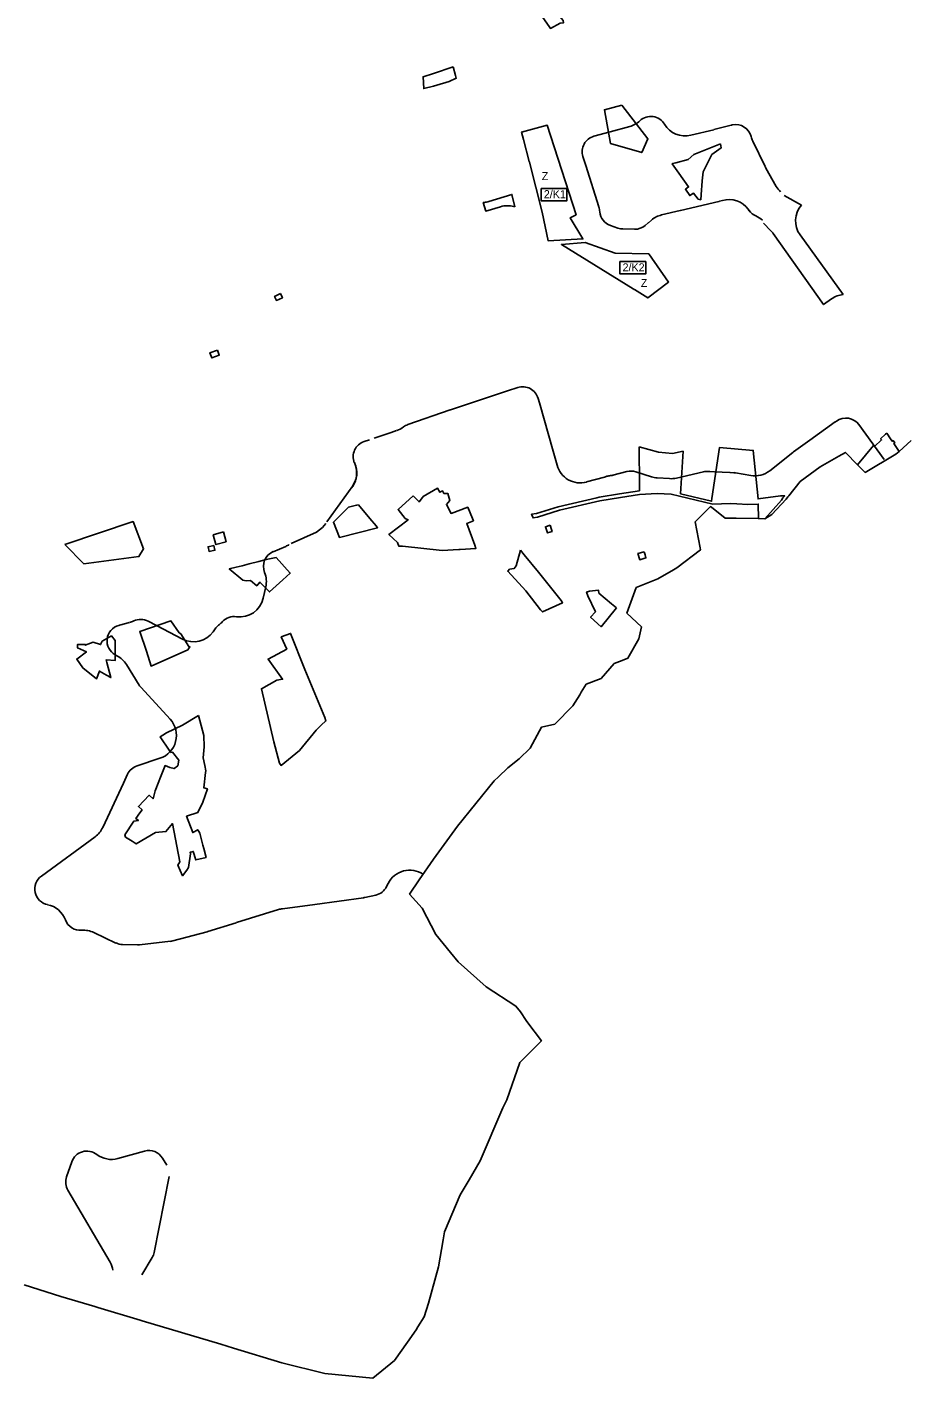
# Model space of a CAD drawing. Extents: x -445049 to -440454, y -1148980 to -1129741.
# Drawn here: x -444109 to -443013, y -1134562 to -1132874 of the extents above; entities that cross this region are included whole.
import ezdxf

# ---------------------------------------------------------------- set-up
doc = ezdxf.new("R2010")
doc.units = 0
for name, color, linetype in [('Vrstva 10', 7, 'Continuous'), ('Vrstva 23', 7, 'Continuous'), ('Vrstva 3', 7, 'Continuous'), ('Vrstva 4', 7, 'Continuous'), ('Vrstva 5', 7, 'Continuous'), ('Vrstva 7', 7, 'Continuous')]:
    doc.layers.add(name, color=color, linetype=linetype)

msp = doc.modelspace()

# ---------------------------------------------------------------- linework, layer by layer
at = {"layer": 'Vrstva 10'}
msp.add_lwpolyline([(-443488.7, -1133014.5), (-443481.6, -1133042.2), (-443481.3, -1133043.2), (-443465.2, -1133105.3), (-443458.1, -1133141.1), (-443414.4, -1133138.9), (-443430.2, -1133112.5), (-443423.1, -1133108.7), (-443459, -1132996.9), (-443491.2, -1133005.4)], close=True, dxfattribs=at)
for points in [[(-443350.1, -1133202.2), (-443333.3, -1133212.6), (-443307.4, -1133192.8), (-443332.2, -1133157.5), (-443374, -1133156.8), (-443411.5, -1133143.2), (-443441.4, -1133145.7), (-443351.7, -1133201.2)], [(-443351.7, -1133201.2), (-443350.4, -1133202)], [(-443350.4, -1133202), (-443350.1, -1133202.2)]]:
    msp.add_lwpolyline(points, dxfattribs=at)
at = {"layer": 'Vrstva 23'}
for p, q in [((-443380.3, -1133005), (-443356, -1132998.4)), ((-443279.4, -1133009.4), (-443251, -1133002.4)), ((-443250.6, -1133002.3), (-443229.1, -1132996.8)), ((-443228.1, -1132996.5), (-443227.4, -1132996.4)), ((-443400.7, -1133010.6), (-443380.4, -1133005)), ((-443202, -1133016.6), (-443186.8, -1133048.4)), ((-443411, -1133047), (-443414.4, -1133035.9)), ((-443394.7, -1133099), (-443410.9, -1133047)), ((-443185.8, -1133050.4), (-443172.7, -1133073.2)), ((-443162.9, -1133084.6), (-443141.3, -1133096.6)), ((-443499.6, -1133098.8), (-443500.8, -1133098.5)), ((-443292.7, -1133103.5), (-443316.1, -1133109)), ((-443244.5, -1133092.1), (-443292.6, -1133103.5)), ((-443240, -1133090.8), (-443243.7, -1133091.9)), ((-443206.6, -1133103.6), (-443207.8, -1133101.9)), ((-443332.7, -1133118.7), (-443336.6, -1133122)), ((-443328.7, -1133115.3), (-443332.6, -1133118.6)), ((-443179.4, -1133128.9), (-443188.7, -1133119.2)), ((-443370.7, -1133125.4), (-443380.1, -1133122.1)), ((-443350, -1133126.8), (-443364.5, -1133126.5)), ((-443143, -1133133.8), (-443089, -1133208.5)), ((-443580.1, -1133352.5), (-443508.6, -1133328.8)), ((-443508.6, -1133328.8), (-443496, -1133324.6)), ((-443470.4, -1133338.2), (-443468.9, -1133343.7)), ((-443633.3, -1133370.9), (-443580.4, -1133352.6)), ((-443468.9, -1133343.8), (-443451.7, -1133404)), ((-443098.9, -1133367.5), (-443097.4, -1133366.4)), ((-443069.5, -1133370.9), (-443037.8, -1133414.4)), ((-443688.1, -1133392.1), (-443681.1, -1133389.8)), ((-443688.1, -1133392.1), (-443682.5, -1133390.2)), ((-443675.3, -1133387.8), (-443654.3, -1133380.7)), ((-443654.3, -1133380.7), (-443647.3, -1133378.3)), ((-443451.6, -1133404.2), (-443446.8, -1133421.6)), ((-443180.9, -1133428.5), (-443152.1, -1133405.6)), ((-443409.9, -1133442.6), (-443387.3, -1133436.4)), ((-443376.9, -1133434.1), (-443359.4, -1133429.6)), ((-443348.4, -1133429.9), (-443328.7, -1133436.1)), ((-443321.6, -1133437.4), (-443306.4, -1133438.4)), ((-443297.6, -1133437.7), (-443263.9, -1133429.8)), ((-443258.4, -1133429.3), (-443255.8, -1133429.4)), ((-443255.7, -1133429.4), (-443250, -1133429.7)), ((-443250, -1133429.7), (-443230.8, -1133430.7)), ((-443230.6, -1133430.7), (-443225.9, -1133431)), ((-443223.8, -1133431.2), (-443204.7, -1133434.5)), ((-443734.6, -1133492.2), (-443702, -1133447.6)), ((-443779.1, -1133519.4), (-443747.5, -1133505.4)), ((-443801.7, -1133529.7), (-443786, -1133523.1)), ((-443814.1, -1133587.8), (-443810.9, -1133573.7)), ((-443994.5, -1133621.8), (-443993.7, -1133621.6)), ((-443993.7, -1133621.6), (-443986, -1133619.5)), ((-443986, -1133619.5), (-443981.5, -1133618.3)), ((-443876.7, -1133629.8), (-443873.2, -1133624.9)), ((-443996.3, -1133660.1), (-443999, -1133658.6)), ((-443969.1, -1133696.5), (-443985.2, -1133670.6)), ((-443930.5, -1133739.1), (-443966.9, -1133699.4)), ((-443971.9, -1133797.3), (-443943.2, -1133787.8)), ((-444091.4, -1133935), (-444024.2, -1133885.8)), ((-443658, -1133944.3), (-443659.9, -1133948.1)), ((-443688.7, -1133962), (-443749.6, -1133970.4)), ((-443673.5, -1133958.7), (-443687, -1133961.7)), ((-443795.1, -1133976.9), (-443847.7, -1133993.1)), ((-443749.7, -1133970.4), (-443790.2, -1133975.8)), ((-443847.9, -1133993.2), (-443883.4, -1134004.4)), ((-443998.2, -1134018.6), (-444025.9, -1134005.5)), ((-443884.3, -1134004.6), (-443927.2, -1134016)), ((-443971.2, -1134020.9), (-443990.1, -1134020.5)), ((-443930.1, -1134016.5), (-443968.6, -1134020.8)), ((-443995.8, -1134287.9), (-443962.5, -1134278.5)), ((-444059.9, -1134310.8), (-444053.4, -1134292)), ((-443939.9, -1134287.4), (-443934.6, -1134296.2)), ((-443931.7, -1134310.2), (-443950.4, -1134405.2)), ((-444005.6, -1134417.5), (-444058.3, -1134327.5)), ((-443952.8, -1134411.5), (-443965.8, -1134433.4))]:
    msp.add_line(p, q, dxfattribs=at)
for points in [[(-443532.2, -1133092.2), (-443503.2, -1133083.2), (-443499.6, -1133098.8)], [(-443517.4, -1133098.7), (-443536, -1133104.2), (-443539, -1133093.5), (-443537.4, -1133093.3)], [(-443103.8, -1133213.9), (-443113.6, -1133220.9), (-443176.6, -1133132.3)], [(-443151.3, -1133405), (-443130.7, -1133390.3), (-443099, -1133367.6)], [(-443703.3, -1133449.6), (-443699.8, -1133443.4), (-443698.1, -1133438.3), (-443697.5, -1133434.5), (-443697.5, -1133428.8), (-443698, -1133425), (-443698.8, -1133422.2), (-443700.2, -1133418.4)], [(-443747.5, -1133505.4), (-443740.1, -1133499.4), (-443735.8, -1133494.3)], [(-443958, -1133616.5), (-443947.5, -1133621.9), (-443915, -1133638.9)], [(-444014.8, -1133874.3), (-443988.8, -1133818.7), (-443983.7, -1133807.8)]]:
    msp.add_lwpolyline(points, dxfattribs=at)
msp.add_lwpolyline([(-444062.3, -1133520.6), (-444038.2, -1133545), (-443969.5, -1133535.7), (-443963.6, -1133526.2), (-443976.9, -1133492)], close=True, dxfattribs=at)
for centre, radius, start, end in [((-443329.5, -1133005.9), 20, 30.8136, 133.2656), ((-443363.8, -1132969.5), 30, 285.0708, 313.2656), ((-443286.6, -1132980.3), 30, 210.8136, 283.8005), ((-443258.1, -1132973.3), 30, 283.8005, 284.5276), ((-443224.1, -1133016.1), 20, 101.4436, 104.5276), ((-443223.4, -1133016), 20, 14.2371, 101.4436), ((-443395.4, -1133029.9), 20, 105.477, 197.5121), ((-443375.1, -1133024.3), 20, 105.0708, 105.477), ((-443175, -1133003.7), 30, 194.2371, 205.5455), ((-443439.6, -1133056), 30, 17.38, 17.5121), ((-443159.8, -1133035.5), 30, 205.5455, 209.8821), ((-443146.7, -1133058.3), 30, 209.8821, 226.7245), ((-443541.1, -1133063.6), 30, 277.0607, 287.2397), ((-443508.8, -1133127.4), 30, 74.5325, 106.7342), ((-443423.3, -1133108), 30, 5.5239, 17.38), ((-443297.2, -1133084), 20, 283.086, 283.374), ((-443249.1, -1133072.6), 20, 283.374, 285.539), ((-443231.9, -1133119.7), 30, 36.3383, 105.539), ((-443190.5, -1133091.7), 20, 216.3383, 246.7557), ((-443118.7, -1133116.3), 30, 138.9795, 215.8663), ((-443373.5, -1133103.2), 20, 185.5239, 250.7766), ((-443313.3, -1133141.5), 30, 130.1903, 130.4326), ((-443309.3, -1133138.2), 30, 103.086, 130.1903), ((-443210.2, -1133137.7), 30, 48.0185, 66.7557), ((-443364.1, -1133106.5), 20, 250.7766, 268.784), ((-443349.6, -1133106.8), 20, 268.784, 310.4326), ((-443201, -1133149.7), 30, 35.4139, 43.9419), ((-443086.4, -1133238.3), 30, 95.036, 125.4139), ((-443489.7, -1133343.6), 20, 15.6761, 108.4331), ((-443518.1, -1133300.3), 30, 288.3161, 288.4331), ((-443573.8, -1133371.5), 20, 108.3161, 109.0994), ((-443440, -1133335.6), 30, 195.6761, 195.9557), ((-443656.9, -1133349.9), 30, 288.7113, 307.1241), ((-443626.7, -1133389.8), 20, 109.0994, 127.1241), ((-443116.4, -1133343.2), 30, 305.6204, 305.8262), ((-443085.7, -1133382.7), 20, 36.0604, 125.8262), ((-443663.9, -1133352.3), 30, 288.6899, 288.7113), ((-443681.7, -1133411.1), 20, 108.6689, 201.6607), ((-443470.9, -1133409.5), 20, 15.2701, 15.9557), ((-443139.6, -1133421.3), 20, 125.615, 128.3723), ((-443726.3, -1133431.5), 29.2, 325.3968, 24.5589), ((-443417.9, -1133413.7), 30, 195.2701, 285.3949), ((-443395.3, -1133407.5), 30, 285.3949, 289.0956), ((-443378.9, -1133454.7), 20, 96.1778, 109.0956), ((-443384.3, -1133405), 30, 276.1778, 284.3857), ((-443354.4, -1133449), 20, 72.539, 104.3857), ((-443319.7, -1133407.5), 30, 252.539, 266.3185), ((-443304.4, -1133408.5), 30, 266.3185, 283.2162), ((-443259.4, -1133449.3), 20, 87.2484, 103.2162), ((-443256.8, -1133449.4), 20, 87.0859, 87.2484), ((-443248.5, -1133399.7), 30, 267.0859, 267.1026), ((-443231.8, -1133450.6), 20, 86.42, 87.1026), ((-443227.2, -1133450.9), 20, 80.1563, 86.42), ((-443199.6, -1133405), 30, 260.1563, 308.3723), ((-443797.6, -1133495.4), 30, 292.7175, 302.2779), ((-443793.9, -1133548.1), 20, 112.7175, 202.2863), ((-443840.2, -1133567.1), 30, 347.314, 22.2863), ((-443843.4, -1133581.2), 30, 261.899, 347.314), ((-443850.4, -1133630.7), 20, 81.899, 136.8487), ((-443989.4, -1133641.1), 20, 104.9329, 241.2863), ((-443988.6, -1133640.9), 20, 104.9278, 104.9329), ((-443980.8, -1133638.8), 20, 104.9064, 104.9278), ((-443989.2, -1133589.3), 30, 284.9064, 296.1072), ((-443967.2, -1133634.2), 20, 62.4796, 116.1072), ((-443857, -1133636.6), 20, 126.7808, 144.2729), ((-443886.9, -1133596.5), 30, 306.7808, 316.8487), ((-443901.1, -1133612.3), 30, 242.4843, 324.2729), ((-444010.7, -1133686.4), 30, 31.8759, 61.2863), ((-443952.1, -1133685.9), 20, 211.8759, 222.5089), ((-443952.6, -1133759.3), 30, 288.2831, 42.5089), ((-443965.6, -1133816.3), 20, 108.2831, 154.9668), ((-444042, -1133861.6), 30, 306.1984, 334.9589), ((-443631.1, -1133957.6), 30, 55.8038, 153.678), ((-444079.6, -1133951.1), 20, 126.1984, 258.4959), ((-443677.8, -1133939.2), 20, 282.5288, 333.678), ((-443691.4, -1133942.2), 20, 277.8092, 282.5288), ((-444089.6, -1134000.1), 30, 20.3417, 78.4959), ((-443786.2, -1134005.5), 30, 97.595, 107.1299), ((-443752.4, -1133950.6), 20, 277.595, 277.8092), ((-444042.7, -1133982.8), 20, 200.3417, 274.5583), ((-443838.9, -1134021.8), 30, 107.1299, 107.4963), ((-444038.7, -1134032.6), 30, 64.6655, 94.5583), ((-443889.4, -1133985.3), 20, 284.8518, 287.4963), ((-443989.6, -1134000.5), 20, 244.6655, 268.7454), ((-443970.8, -1134000.9), 20, 268.7454, 276.3369), ((-443932.3, -1133996.7), 20, 276.3369, 284.8518), ((-444034.5, -1134298.6), 20, 52.3247, 160.864), ((-444003.9, -1134259), 30, 232.3247, 285.7015), ((-443957.1, -1134297.8), 20, 31.1463, 105.7015), ((-444041, -1134317.4), 20, 160.864, 210.3258), ((-444031.5, -1134432.6), 30, 10.3353, 30.3258), ((-443970, -1134401.3), 20, 329.2942, 348.8542)]:
    msp.add_arc(centre, radius, start, end, dxfattribs=at)
at = {"layer": 'Vrstva 3'}
for points in [[(-443466.5, -1133075.8), (-443434.4, -1133075.8), (-443434.4, -1133091.2), (-443466.5, -1133091.2)], [(-443368.1, -1133167.2), (-443335.9, -1133167.2), (-443335.9, -1133182.6), (-443368.1, -1133182.6)]]:
    msp.add_lwpolyline(points, close=True, dxfattribs=at)
at = {"layer": 'Vrstva 5'}
msp.add_lwpolyline([(-444112.9, -1134445.6), (-444067.3, -1134460.2), (-444024.8, -1134472.9), (-444020.9, -1134474), (-443968, -1134489.8), (-443965.3, -1134490.6), (-443866.9, -1134520), (-443851.3, -1134524.7), (-443791, -1134543.3), (-443737, -1134556.5), (-443676.9, -1134562.1), (-443649.8, -1134540.2), (-443633.9, -1134517.4), (-443623.1, -1134502.1), (-443620.7, -1134498.1), (-443613, -1134485.6), (-443607.6, -1134468.5), (-443594.8, -1134423.4), (-443589.3, -1134389.5), (-443587.7, -1134379.4), (-443567.8, -1134333.2), (-443556.7, -1134314.5), (-443542.7, -1134290.9), (-443514.7, -1134224.7), (-443509.6, -1134214.4), (-443493.3, -1134168), (-443466.4, -1134140.8), (-443483.2, -1134118.2), (-443485.3, -1134115.3), (-443492.5, -1134104.8), (-443498.3, -1134097.4), (-443535.5, -1134073.4), (-443570.5, -1134042.3), (-443579.9, -1134030.6), (-443598.2, -1134007.9), (-443615.3, -1133975.2), (-443631.1, -1133957.6), (-443619, -1133939.8), (-443601.3, -1133913.7), (-443571.4, -1133872.6), (-443525.4, -1133816.1), (-443519.9, -1133810.9), (-443508.5, -1133799.8), (-443494.1, -1133788.5), (-443480.2, -1133775), (-443468.6, -1133753.3), (-443466.2, -1133748.9), (-443449.4, -1133745.1), (-443427.1, -1133722.1), (-443418.4, -1133708.5), (-443416.5, -1133705.4), (-443410.3, -1133695.4), (-443391.7, -1133688.2), (-443375.3, -1133669.3), (-443365.3, -1133665.5), (-443358.3, -1133662.8), (-443344.7, -1133638.5), (-443341.3, -1133623.4), (-443359.4, -1133606.5), (-443347.8, -1133574.5), (-443320.6, -1133563.8), (-443301.3, -1133552.4), (-443297.2, -1133549.9), (-443267.5, -1133527.5), (-443268, -1133524.7), (-443274.1, -1133492.3), (-443262.4, -1133480.8), (-443254.8, -1133473.4), (-443251.5, -1133475.9), (-443236.6, -1133487.6), (-443223, -1133487.8), (-443195.1, -1133488.4), (-443187.2, -1133488.5), (-443178.2, -1133483.2), (-443160.5, -1133463.9), (-443158.2, -1133461.2), (-443157.2, -1133459.9), (-443143, -1133442.1), (-443118, -1133423.7), (-443094.7, -1133410.5), (-443086.4, -1133405.7), (-443071.4, -1133421), (-443061.5, -1133430.7), (-443023.3, -1133407.9), (-443019.2, -1133404.3), (-443014, -1133399.8), (-443004.2, -1133390.8)], dxfattribs=at)
at = {"layer": 'Vrstva 7'}
for points in [[(-443451.5, -1132851.1), (-443464.6, -1132862.4), (-443456.8, -1132873.4), (-443455.1, -1132875.9), (-443443.1, -1132869.2), (-443438.8, -1132869), (-443439, -1132866.2)], [(-443576.6, -1132924), (-443601.3, -1132932.4), (-443614.2, -1132936.3), (-443613.5, -1132951), (-443601.2, -1132948), (-443596.9, -1132946.9), (-443581.6, -1132942.4), (-443572.9, -1132938.2), (-443573.8, -1132934.8)], [(-443365.7, -1132971.7), (-443387.5, -1132977.5), (-443379.8, -1133019.8), (-443341, -1133031), (-443333.3, -1133014)], [(-443242.5, -1133019.9), (-443275.6, -1133033.4), (-443282.8, -1133039.8), (-443298.4, -1133043.8), (-443302.3, -1133044.8), (-443303, -1133045.1), (-443294.6, -1133056.9), (-443282.3, -1133074), (-443286.4, -1133076.9), (-443280.8, -1133084.8), (-443276.3, -1133081.6), (-443270.5, -1133089.1), (-443267.2, -1133089.9), (-443266.2, -1133077.4), (-443265.7, -1133072.4), (-443265.2, -1133066.4), (-443264.3, -1133055.1), (-443263, -1133052.5), (-443253.5, -1133033.6), (-443241.8, -1133025.3)], [(-443792.4, -1133207.3), (-443799.9, -1133210.8), (-443797.7, -1133215.8), (-443790.1, -1133212.3)], [(-443871.2, -1133277.7), (-443880.8, -1133281.2), (-443878.5, -1133287.5), (-443869, -1133284)], [(-443034.7, -1133381.4), (-443036.3, -1133383), (-443042.4, -1133388.6), (-443041, -1133390), (-443049.8, -1133398.3), (-443051.1, -1133396.8), (-443071.4, -1133421), (-443061.5, -1133430.7), (-443023.3, -1133407.9), (-443019.2, -1133404.3), (-443025.8, -1133394.6), (-443024.7, -1133393.8), (-443026.7, -1133390.9), (-443027.8, -1133391.7), (-443029.8, -1133388.6)], [(-443344.3, -1133398.7), (-443343.9, -1133447.1), (-443343.9, -1133450.5), (-443343.9, -1133453.6), (-443368.6, -1133457.3), (-443394, -1133461.6), (-443397, -1133462.3), (-443445.4, -1133473.6), (-443472.6, -1133481.9), (-443478.7, -1133482.9), (-443476.7, -1133487.4), (-443471.1, -1133486.5), (-443443.7, -1133477.9), (-443393.4, -1133466.2), (-443367.4, -1133461.9), (-443343.8, -1133458.4), (-443321.8, -1133457.1), (-443304.3, -1133457.9), (-443252.2, -1133470.2), (-443230.3, -1133469.6), (-443222, -1133470), (-443208.1, -1133470.6), (-443195.3, -1133470.3), (-443195.1, -1133488.4), (-443187.2, -1133488.5), (-443166.1, -1133465.1), (-443164.5, -1133462.4), (-443162.2, -1133459.9), (-443167.4, -1133459.9), (-443195.5, -1133463.8), (-443201.6, -1133403.1), (-443243.6, -1133399.5), (-443253.2, -1133463.3), (-443253.7, -1133466.6), (-443292.4, -1133457.2), (-443289.3, -1133404.2), (-443302.5, -1133407.1), (-443319.9, -1133405.4)], [(-443626.7, -1133459.8), (-443645.5, -1133477), (-443636.5, -1133488.4), (-443633.1, -1133489.8), (-443656.9, -1133508), (-443646.3, -1133518.2), (-443644.5, -1133522.8), (-443639.8, -1133522.8), (-443590.5, -1133528.1), (-443569.4, -1133526.9), (-443567.8, -1133526.8), (-443548.3, -1133525.6), (-443549.5, -1133521.6), (-443559.6, -1133494.4), (-443551.4, -1133491.1), (-443552.6, -1133488.2), (-443555.6, -1133481), (-443558.4, -1133474.1), (-443579.2, -1133481.9), (-443585, -1133470.7), (-443580.7, -1133465.9), (-443583.4, -1133456.8), (-443588.2, -1133456.8), (-443590.1, -1133453.6), (-443593.3, -1133455.5), (-443596.2, -1133450.4), (-443614.3, -1133460.9), (-443617.6, -1133465.3), (-443619.2, -1133467.4)], [(-443695.1, -1133471), (-443697.5, -1133471.6), (-443707.4, -1133474), (-443726.3, -1133493), (-443718.8, -1133511.9), (-443671.1, -1133499.8), (-443673.1, -1133497.4), (-443680.8, -1133488.1)], [(-443863.9, -1133505), (-443876.6, -1133508.5), (-443873.3, -1133520.7), (-443860.5, -1133517.2)], [(-443455.6, -1133496.7), (-443461.3, -1133498.6), (-443459.6, -1133503.8), (-443458.8, -1133506.2), (-443453, -1133504.3), (-443453.9, -1133501.9)], [(-443876, -1133521.9), (-443883.1, -1133523.5), (-443881.8, -1133529.4), (-443874.6, -1133527.8)], [(-443798.1, -1133536.8), (-443810.3, -1133539.5), (-443819.6, -1133541.9), (-443831.7, -1133544.9), (-443840.6, -1133547.2), (-443848.1, -1133549.1), (-443856.6, -1133551.3), (-443839.4, -1133565.2), (-443835.3, -1133566.2), (-443830, -1133565.6), (-443822.3, -1133572.3), (-443818.3, -1133567.7), (-443806.3, -1133580), (-443789.4, -1133564.7), (-443780.3, -1133556.5)], [(-443492.5, -1133527.7), (-443497.7, -1133547.5), (-443500.3, -1133550.5), (-443506.1, -1133551.4), (-443508.5, -1133554.2), (-443485.7, -1133578.6), (-443467.3, -1133602.2), (-443465, -1133605), (-443439.8, -1133593.4), (-443441.6, -1133590.8), (-443470, -1133555.4), (-443487.8, -1133533.5)], [(-443338, -1133529.8), (-443345.7, -1133532.1), (-443343.4, -1133539.8), (-443339.5, -1133538.6), (-443335.7, -1133537.4), (-443336.8, -1133533.7)], [(-443372.6, -1133599.9), (-443391.8, -1133623.5), (-443404.9, -1133611.5), (-443398.9, -1133604.7), (-443408.2, -1133584.8), (-443409.8, -1133580.2), (-443406.2, -1133579), (-443395.1, -1133577.6), (-443394.4, -1133581.4), (-443378.7, -1133594.7)], [(-443917.2, -1133632.4), (-443919, -1133631.1), (-443929.6, -1133616.1), (-443968.4, -1133629.2), (-443960.1, -1133653.9), (-443954.3, -1133672.7), (-443908.3, -1133652.2), (-443905.8, -1133648.6), (-443907.3, -1133648.2)], [(-443999.2, -1133640.8), (-444003.9, -1133634.9), (-444015.5, -1133641.6), (-444017.4, -1133645.7), (-444026.5, -1133642.6), (-444036.7, -1133646.5), (-444036.7, -1133645.6), (-444046.1, -1133645.6), (-444046.1, -1133649.9), (-444035.2, -1133655), (-444047.2, -1133663.8), (-444039.7, -1133674.8), (-444022.5, -1133688.4), (-444018.8, -1133678.8), (-444010.2, -1133683.8), (-444004.6, -1133687), (-444009.5, -1133668.1), (-444010.4, -1133664.6), (-443999.3, -1133665.7)], [(-443762.3, -1133677), (-443779.9, -1133631.8), (-443791.6, -1133636.2), (-443784.7, -1133651.4), (-443808.1, -1133663.9), (-443789.9, -1133689.1), (-443797.1, -1133690.3), (-443816.3, -1133700.9), (-443800.7, -1133767.2), (-443793.9, -1133793.9), (-443791.7, -1133796.7), (-443768.8, -1133778), (-443747.8, -1133752.6), (-443741.5, -1133746.5), (-443735.7, -1133741.1), (-443737.2, -1133736.9)], [(-443895.2, -1133734.4), (-443915.1, -1133746.6), (-443934.9, -1133755.8), (-443939.8, -1133759.1), (-443943.1, -1133761.2), (-443931.5, -1133777.6), (-443929.5, -1133780.4), (-443927.4, -1133780.3), (-443919.5, -1133790.1), (-443921, -1133797.2), (-443925.5, -1133800.7), (-443930.8, -1133799.4), (-443936.8, -1133797), (-443942.4, -1133811.4), (-443948.2, -1133826.2), (-443949.1, -1133828.6), (-443951.7, -1133838.4), (-443956.6, -1133833.9), (-443970.1, -1133847.9), (-443965.6, -1133852.3), (-443968.4, -1133856), (-443973.5, -1133863), (-443970.2, -1133865.4), (-443975.7, -1133866.2), (-443987, -1133883.5), (-443986.2, -1133886.2), (-443978, -1133891.5), (-443973, -1133894.9), (-443948.6, -1133880.5), (-443935.8, -1133879.3), (-443927.7, -1133869.4), (-443918.5, -1133917.2), (-443921, -1133921.4), (-443915.1, -1133934.6), (-443909.7, -1133927.4), (-443907.4, -1133924.4), (-443904.9, -1133907.2), (-443905.5, -1133905.2), (-443904.5, -1133905), (-443901.5, -1133904.2), (-443898.5, -1133914.8), (-443885.5, -1133911.6), (-443888.3, -1133900.6), (-443889.4, -1133896.3), (-443893.3, -1133881.4), (-443896, -1133877.1), (-443902.3, -1133880.7), (-443910, -1133860.2), (-443895.8, -1133855.4), (-443889.8, -1133842.6), (-443883.9, -1133826.1), (-443888.2, -1133824.8), (-443886.1, -1133805.5), (-443885.9, -1133803.6), (-443886.9, -1133796.9), (-443889.1, -1133787.3), (-443887.8, -1133773.7), (-443888.3, -1133759.5)]]:
    msp.add_lwpolyline(points, close=True, dxfattribs=at)

# ---------------------------------------------------------------- texts
at = {"layer": 'Vrstva 3'}
for s, p in [('2/K1', (-443463.3, -1133088)), ('2/K2', (-443364.9, -1133179.4))]:
    msp.add_text(s, height=10, dxfattribs=at).set_placement(p)
at = {"layer": 'Vrstva 4'}
for p in [(-443465.9, -1133065.4), (-443342.1, -1133199)]:
    msp.add_text('Z', height=10, dxfattribs=at).set_placement(p)

doc.saveas('drawing.dxf')
